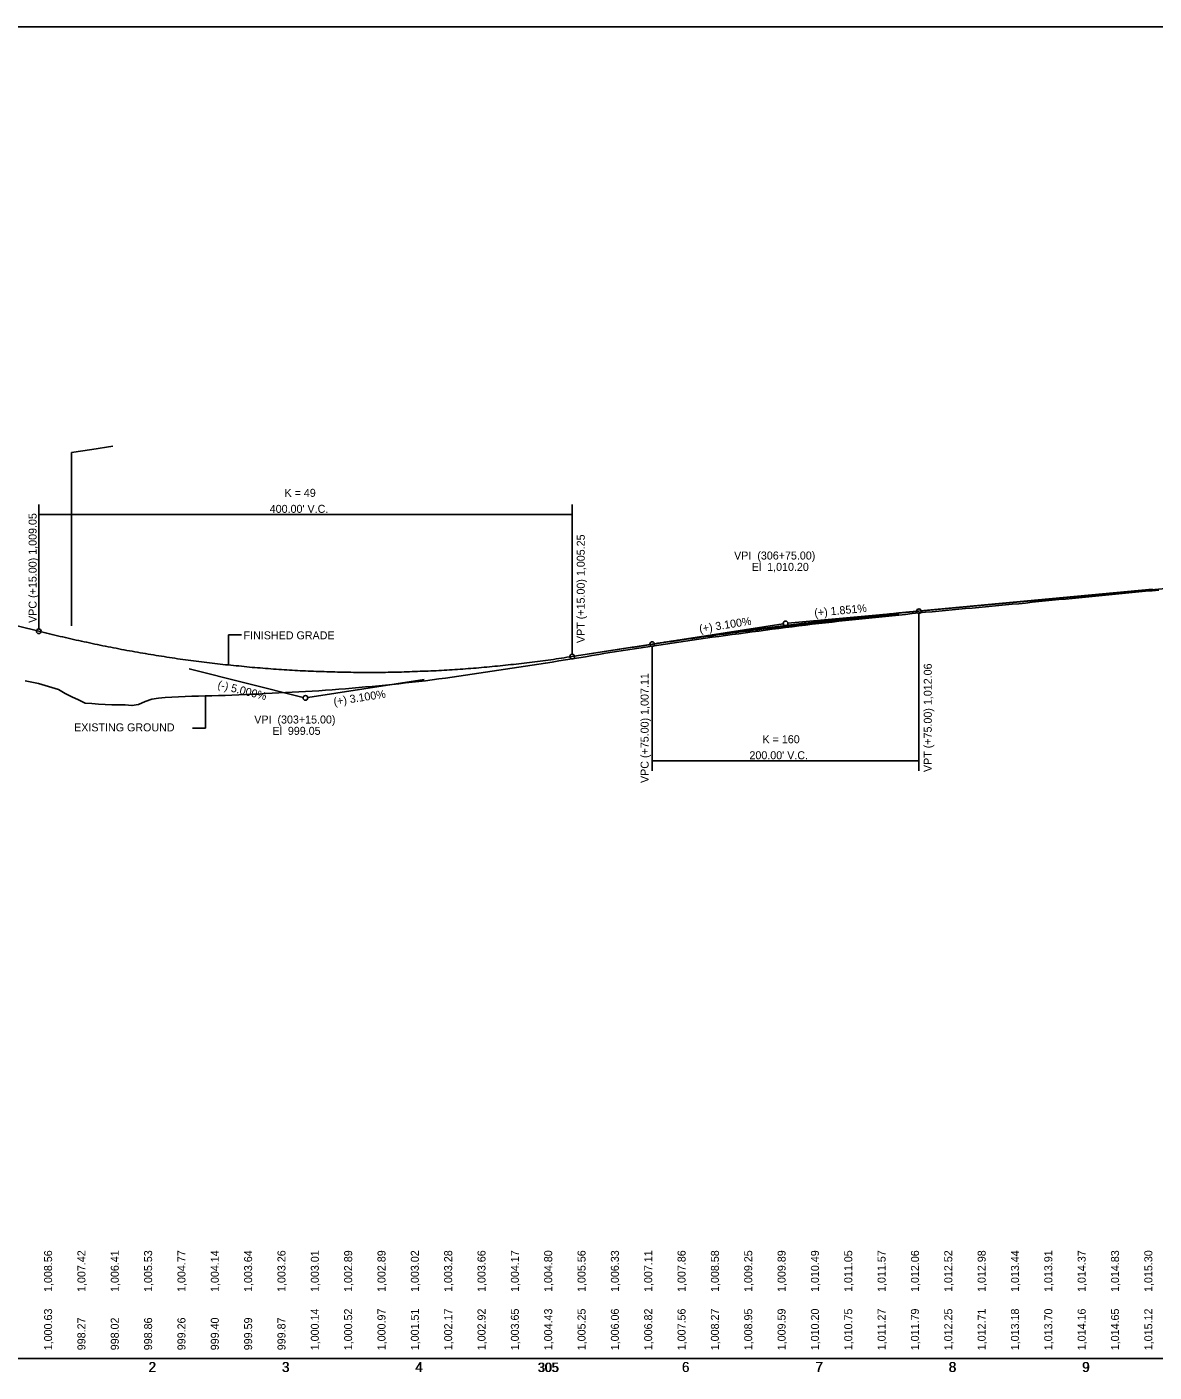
# Model space of a CAD drawing. Extents: x 112 to 16977479, y 1011 to 12562669.
# Drawn here: x 16974487 to 16975332, y 12561659 to 12562667 of the extents above; entities that cross this region are included whole.
import ezdxf

# ---------------------------------------------------------------- set-up
doc = ezdxf.new("R2010")
doc.units = 0
for name, color, linetype in [('Default', 7, 'Continuous'), ('RD_DDB_Ex_Tx', 7, 'Continuous'), ('RD_DDB_GradeTX', 7, 'Continuous'), ('RD_DDB_PI', 7, 'Continuous'), ('RD_DDB_Pr_Tx', 7, 'Continuous'), ('RD_DDB_Profile_EX', 7, 'Continuous'), ('RD_DDB_Profile_PR', 7, 'Continuous'), ('RD_DDB_StaTX', 7, 'Continuous'), ('RD_DDB_StripGrade_EX', 7, 'Continuous'), ('RD_DDB_StripGrade_PR', 7, 'Continuous'), ('RD_DDB_VCLbl', 7, 'Continuous'), ('RD_GPK_Profile_Cell', 7, 'Continuous'), ('RD_Sketch1', 7, 'Continuous')]:
    doc.layers.add(name, color=color, linetype=linetype)

msp = doc.modelspace()

# ---------------------------------------------------------------- linework, layer by layer
at = {"layer": 'Default'}
for p, q in [((16975140.4, 12562227.9), (16975330.4, 12562245.7)), ((16974895.4, 12562195.2), (16974940.4, 12562202.1))]:
    msp.add_line(p, q, dxfattribs=at)
msp.add_lwpolyline([(16974478.7, 12561668.9), (16975978.7, 12561668.9), (16975978.7, 12562667.2), (16974478.7, 12562667.2)], close=True, dxfattribs=at)
msp.add_open_spline([(16974940.4, 12562202.1), (16975040.4, 12562217.6), (16975140.4, 12562227)], degree=2, dxfattribs=at)
at = {"layer": 'RD_DDB_Ex_Tx'}
for p, q in [((16974620.5, 12562141.6), (16974620.5, 12562165.5)), ((16974610.8, 12562141.6), (16974620.5, 12562141.6))]:
    msp.add_line(p, q, dxfattribs=at)
at = {"layer": 'RD_DDB_PI'}
for p, q in [((16975145, 12562228.3), (16975057.1, 12562220.1)), ((16974966.5, 12562206.2), (16975053.7, 12562219.7)), ((16974608.1, 12562186), (16974693.7, 12562164.6)), ((16974784.3, 12562177.9), (16974697.1, 12562164.4))]:
    msp.add_line(p, q, dxfattribs=at)
for centre in [(16975055.4, 12562220), (16974695.4, 12562164.2)]:
    msp.add_circle(centre, 1.75, dxfattribs=at)
at = {"layer": 'RD_DDB_Pr_Tx'}
for p, q in [((16974647.5, 12562211.4), (16974637.6, 12562211.4)), ((16974637.6, 12562211.4), (16974637.6, 12562188.9))]:
    msp.add_line(p, q, dxfattribs=at)
at = {"layer": 'RD_DDB_Profile_EX'}
for points in [[(16975115.3, 12562223.8), (16975120.3, 12562224.3), (16975125.3, 12562224.8), (16975130.3, 12562225.3), (16975135.3, 12562225.8), (16975140.3, 12562226.3), (16975145.3, 12562226.8), (16975150.3, 12562227.4), (16975155.3, 12562227.9), (16975160.3, 12562228.4), (16975165.3, 12562228.8), (16975170.3, 12562229.3), (16975175.3, 12562229.7), (16975180.3, 12562230.2), (16975185.3, 12562230.6), (16975190.3, 12562231.1), (16975195.3, 12562231.5), (16975200.3, 12562232), (16975205.3, 12562232.5), (16975210.3, 12562232.9), (16975215.3, 12562233.4), (16975220.3, 12562233.9), (16975225.3, 12562234.4), (16975230.3, 12562234.8), (16975235.3, 12562235.3), (16975240.3, 12562235.9), (16975245.3, 12562236.4), (16975250.3, 12562236.9), (16975255.3, 12562237.4), (16975260.3, 12562237.9), (16975265.3, 12562238.3), (16975270.3, 12562238.8), (16975275.3, 12562239.3), (16975280.3, 12562239.7), (16975285.3, 12562240.2), (16975290.3, 12562240.7), (16975295.3, 12562241.2), (16975300.3, 12562241.7), (16975305.3, 12562242.2), (16975310.3, 12562242.7), (16975315.3, 12562243.2), (16975320.3, 12562243.6), (16975325.3, 12562244.1), (16975330.3, 12562244.5), (16975335.3, 12562244.9)], [(16974615.3, 12562165.5), (16974620.3, 12562165.7), (16974625.3, 12562165.8), (16974630.3, 12562166), (16974635.3, 12562166.1), (16974640.3, 12562166.3), (16974645.3, 12562166.5), (16974650.3, 12562166.7), (16974655.3, 12562166.9), (16974660.3, 12562167.1), (16974665.3, 12562167.4), (16974670.3, 12562167.7), (16974675.3, 12562168), (16974680.3, 12562168.3), (16974685.3, 12562168.5), (16974690.3, 12562168.7), (16974695.3, 12562169), (16974700.3, 12562169.3), (16974705.3, 12562169.6), (16974710.3, 12562170), (16974715.3, 12562170.3), (16974720.3, 12562170.7), (16974725.3, 12562171.1), (16974730.3, 12562171.5), (16974735.3, 12562172), (16974740.3, 12562172.4), (16974745.3, 12562172.8), (16974750.3, 12562173.3), (16974755.3, 12562173.8), (16974760.3, 12562174.3), (16974765.3, 12562174.8), (16974770.3, 12562175.4), (16974775.3, 12562175.9), (16974780.3, 12562176.5), (16974785.3, 12562177.1), (16974790.3, 12562177.8), (16974795.3, 12562178.5), (16974800.3, 12562179.1), (16974805.3, 12562179.8), (16974810.3, 12562180.5), (16974815.3, 12562181.2), (16974820.3, 12562182), (16974825.3, 12562182.8), (16974830.3, 12562183.5), (16974835.3, 12562184.3), (16974840.3, 12562185), (16974845.3, 12562185.7), (16974850.3, 12562186.5), (16974855.3, 12562187.2), (16974860.3, 12562187.9), (16974865.3, 12562188.7), (16974870.3, 12562189.4), (16974875.3, 12562190.3), (16974880.3, 12562191.1), (16974885.3, 12562191.9), (16974890.3, 12562192.7), (16974895.3, 12562193.5), (16974900.3, 12562194.3), (16974905.3, 12562195.1), (16974910.3, 12562196), (16974915.3, 12562196.8), (16974920.3, 12562197.6), (16974925.3, 12562198.4), (16974930.3, 12562199.2), (16974935.3, 12562200), (16974940.3, 12562200.7), (16974945.3, 12562201.5), (16974950.3, 12562202.2), (16974955.3, 12562203), (16974960.3, 12562203.7), (16974965.3, 12562204.5), (16974970.3, 12562205.2), (16974975.3, 12562206), (16974980.3, 12562206.7), (16974985.3, 12562207.4), (16974990.3, 12562208.2), (16974995.3, 12562208.9), (16975000.3, 12562209.6), (16975005.3, 12562210.3), (16975010.3, 12562211), (16975015.3, 12562211.7), (16975020.3, 12562212.3), (16975025.3, 12562213), (16975030.3, 12562213.6), (16975035.3, 12562214.3), (16975040.3, 12562214.9), (16975045.3, 12562215.6), (16975050.3, 12562216.2), (16975055.3, 12562216.9), (16975060.3, 12562217.5), (16975065.3, 12562218.2), (16975070.3, 12562218.8), (16975075.3, 12562219.4), (16975080.3, 12562219.9), (16975085.3, 12562220.5), (16975090.3, 12562221), (16975095.3, 12562221.6), (16975100.3, 12562222.1), (16975105.3, 12562222.7), (16975110.3, 12562223.2), (16975115.3, 12562223.8)], [(16974485.3, 12562177), (16974490.3, 12562175.9), (16974495.3, 12562174.9), (16974500.3, 12562173.5), (16974505.3, 12562172.1), (16974510.3, 12562170.4), (16974515.3, 12562167.5), (16974520.3, 12562165), (16974525.3, 12562162.8), (16974530.3, 12562160.3), (16974535.3, 12562159.9), (16974540.3, 12562159.6), (16974545.3, 12562159.3), (16974550.3, 12562159), (16974555.3, 12562159), (16974560.3, 12562159.1), (16974565.3, 12562158.4), (16974570.3, 12562159.3), (16974575.3, 12562161.5), (16974580.3, 12562163.2), (16974585.3, 12562164), (16974590.3, 12562164.5), (16974595.3, 12562164.7), (16974600.3, 12562165), (16974605.3, 12562165.2), (16974610.3, 12562165.4), (16974615.3, 12562165.5)]]:
    msp.add_lwpolyline(points, dxfattribs=at)
at = {"layer": 'RD_DDB_Profile_PR'}
for p, q in [((16975155.4, 12562229.2), (16975340.4, 12562246.3)), ((16974450.4, 12562225.4), (16974495.4, 12562214.2)), ((16974895.4, 12562195.2), (16974955.4, 12562204.5))]:
    msp.add_line(p, q, dxfattribs=at)
for points in [[(16974955.4, 12562204.5), (16974959.4, 12562205.1), (16974963.4, 12562205.7), (16974967.4, 12562206.3), (16974971.4, 12562206.9), (16974975.4, 12562207.5), (16974979.4, 12562208.1), (16974983.4, 12562208.7), (16974987.4, 12562209.3), (16974991.4, 12562209.8), (16974995.4, 12562210.4), (16974999.4, 12562211), (16975003.4, 12562211.5), (16975007.4, 12562212.1), (16975011.4, 12562212.7), (16975015.4, 12562213.2), (16975019.4, 12562213.7), (16975023.4, 12562214.3), (16975027.4, 12562214.8), (16975031.4, 12562215.3), (16975035.4, 12562215.9), (16975039.4, 12562216.4), (16975043.4, 12562216.9), (16975047.4, 12562217.4), (16975051.4, 12562217.9), (16975055.4, 12562218.4), (16975059.4, 12562218.9), (16975063.4, 12562219.4), (16975067.4, 12562219.9), (16975071.4, 12562220.3), (16975075.4, 12562220.8), (16975079.4, 12562221.3), (16975083.4, 12562221.7), (16975087.4, 12562222.2), (16975091.4, 12562222.7), (16975095.4, 12562223.1), (16975099.4, 12562223.5), (16975103.4, 12562224), (16975107.4, 12562224.4), (16975111.4, 12562224.8), (16975115.4, 12562225.3), (16975119.4, 12562225.7), (16975123.4, 12562226.1), (16975127.4, 12562226.5), (16975131.4, 12562226.9), (16975135.4, 12562227.3), (16975139.4, 12562227.7), (16975143.4, 12562228.1), (16975147.4, 12562228.5), (16975151.4, 12562228.8), (16975155.4, 12562229.2)], [(16974495.4, 12562214.2), (16974503.4, 12562212.2), (16974511.4, 12562210.3), (16974519.4, 12562208.5), (16974527.4, 12562206.7), (16974535.4, 12562205), (16974543.4, 12562203.3), (16974551.4, 12562201.8), (16974559.4, 12562200.2), (16974567.4, 12562198.8), (16974575.4, 12562197.4), (16974583.4, 12562196.1), (16974591.4, 12562194.8), (16974599.4, 12562193.6), (16974607.4, 12562192.5), (16974615.4, 12562191.5), (16974623.4, 12562190.5), (16974631.4, 12562189.5), (16974639.4, 12562188.7), (16974647.4, 12562187.9), (16974655.4, 12562187.1), (16974663.4, 12562186.5), (16974671.4, 12562185.8), (16974679.4, 12562185.3), (16974687.4, 12562184.8), (16974695.4, 12562184.4), (16974703.4, 12562184.1), (16974711.4, 12562183.8), (16974719.4, 12562183.6), (16974727.4, 12562183.4), (16974735.4, 12562183.3), (16974743.4, 12562183.3), (16974751.4, 12562183.3), (16974759.4, 12562183.4), (16974767.4, 12562183.6), (16974775.4, 12562183.9), (16974783.4, 12562184.2), (16974791.4, 12562184.5), (16974799.4, 12562184.9), (16974807.4, 12562185.4), (16974815.4, 12562186), (16974823.4, 12562186.6), (16974831.4, 12562187.3), (16974839.4, 12562188.1), (16974847.4, 12562188.9), (16974855.4, 12562189.8), (16974863.4, 12562190.7), (16974871.4, 12562191.7), (16974879.4, 12562192.8), (16974887.4, 12562194), (16974895.4, 12562195.2)]]:
    msp.add_spline(points, degree=3, dxfattribs=at)
at = {"layer": 'RD_DDB_VCLbl'}
for p, q in [((16974495.4, 12562309.2), (16974495.4, 12562215.9)), ((16974895.4, 12562309.2), (16974895.4, 12562196.9)), ((16974495.4, 12562301.7), (16974895.4, 12562301.7)), ((16975155.4, 12562109.5), (16975155.4, 12562227.5)), ((16974955.4, 12562109.5), (16974955.4, 12562202.7)), ((16974955.4, 12562117), (16975155.4, 12562117))]:
    msp.add_line(p, q, dxfattribs=at)
for centre in [(16975155.4, 12562229.2), (16974495.4, 12562214.2), (16974955.4, 12562204.5), (16974895.4, 12562195.2)]:
    msp.add_circle(centre, 1.75, dxfattribs=at)
at = {"layer": 'RD_GPK_Profile_Cell'}
msp.add_line((16973115.3, 12561668.9), (16977337.9, 12561668.9), dxfattribs=at)
at = {"layer": 'RD_Sketch1'}
for p, q in [((16974519.9, 12562348.2), (16974535.1, 12562350.3)), ((16974519.9, 12562348.2), (16974519.9, 12562308.2)), ((16974535.1, 12562350.3), (16974550.9, 12562352.8)), ((16974519.9, 12562308.2), (16974519.9, 12562218.2))]:
    msp.add_line(p, q, dxfattribs=at)

# ---------------------------------------------------------------- texts
at = {"layer": 'RD_DDB_Ex_Tx'}
msp.add_text('EXISTING GROUND', height=6, dxfattribs=at).set_placement((16974521.9, 12562139.1))
at = {"layer": 'RD_DDB_GradeTX'}
for s, rotation, p in [('(+) 1.851%', 5.2881, (16975077.2, 12562225)), ('(+) 3.100%', 8.8105, (16974991.1, 12562213)), ('(-) 5.000%', 345.9641, (16974629.1, 12562171.5)), ('(+) 3.100%', 8.8105, (16974716.9, 12562158.4))]:
    msp.add_text(s, height=6, rotation=rotation, dxfattribs=at).set_placement(p)
at = {"layer": 'RD_DDB_PI'}
for s, p in [('VPI  (306+75.00)', (16975016.8, 12562267.9)), ('El  1,010.20', (16975030, 12562259.4)), ('VPI  (303+15.00)', (16974657, 12562145)), ('El  999.05', (16974670.6, 12562136.5))]:
    msp.add_text(s, height=6, dxfattribs=at).set_placement(p)
at = {"layer": 'RD_DDB_Pr_Tx'}
msp.add_text('FINISHED GRADE', height=6, dxfattribs=at).set_placement((16974649, 12562208.1))
at = {"layer": 'RD_DDB_StaTX'}
for s, height, p in [('2', 7.5, (16974577.6, 12561658.9)), ('2', 7.5, (16974577.6, 12561658.9)), ('2', 7.5, (16974578, 12561658.9)), ('3', 7.5, (16974677.6, 12561658.9)), ('3', 7.5, (16974677.6, 12561658.9)), ('3', 7.5, (16974678, 12561658.9)), ('4', 7.5, (16974777.6, 12561658.9)), ('4', 7.5, (16974777.6, 12561658.9)), ('4', 7.5, (16974778, 12561658.9)), ('305', 7, (16974869.4, 12561658.9)), ('305', 7, (16974869.4, 12561658.9)), ('305', 7, (16974870, 12561658.9)), ('6', 7.5, (16974977.6, 12561658.9)), ('6', 7.5, (16974977.6, 12561658.9)), ('6', 7.5, (16974977.8, 12561658.9)), ('7', 7.5, (16975077.6, 12561658.9)), ('7', 7.5, (16975077.6, 12561658.9)), ('7', 7.5, (16975078, 12561658.9)), ('8', 7.5, (16975177.6, 12561658.9)), ('8', 7.5, (16975177.6, 12561658.9)), ('8', 7.5, (16975178, 12561658.9)), ('9', 7.5, (16975277.6, 12561658.9)), ('9', 7.5, (16975277.6, 12561658.9)), ('9', 7.5, (16975278, 12561658.9))]:
    msp.add_text(s, height=height, dxfattribs=at).set_placement(p)
at = {"layer": 'RD_DDB_StripGrade_EX'}
for s, p in [('1,000.63', (16974505.4, 12561675.2)), ('1,000.14', (16974705.4, 12561675.2)), ('1,000.52', (16974730.4, 12561675.2)), ('1,000.97', (16974755.4, 12561675.2)), ('1,001.51', (16974780.4, 12561675.2)), ('1,002.17', (16974805.4, 12561675.2)), ('1,002.92', (16974830.4, 12561675.2)), ('1,003.65', (16974855.4, 12561675.2)), ('1,004.43', (16974880.4, 12561675.2)), ('1,005.25', (16974905.4, 12561675.2)), ('1,006.06', (16974930.4, 12561675.2)), ('1,006.82', (16974955.4, 12561675.2)), ('1,007.56', (16974980.4, 12561675.2)), ('1,008.27', (16975005.4, 12561675.2)), ('1,008.95', (16975030.4, 12561675.2)), ('1,009.59', (16975055.4, 12561675.2)), ('1,010.20', (16975080.4, 12561675.2)), ('1,010.75', (16975105.4, 12561675.2)), ('1,011.27', (16975130.4, 12561675.2)), ('1,011.79', (16975155.4, 12561675.2)), ('1,012.25', (16975180.4, 12561675.2)), ('1,012.71', (16975205.4, 12561675.2)), ('1,013.18', (16975230.4, 12561675.2)), ('1,013.70', (16975255.4, 12561675.2)), ('1,014.16', (16975280.4, 12561675.2)), ('1,014.65', (16975305.4, 12561675.2)), ('1,015.12', (16975330.4, 12561675.2)), ('998.27', (16974530.4, 12561675.2)), ('998.02', (16974555.4, 12561675.2)), ('998.86', (16974580.4, 12561675.2)), ('999.26', (16974605.4, 12561675.2)), ('999.40', (16974630.4, 12561675.2)), ('999.59', (16974655.4, 12561675.2)), ('999.87', (16974680.4, 12561675.2))]:
    msp.add_text(s, height=6, rotation=90, dxfattribs=at).set_placement(p)
at = {"layer": 'RD_DDB_StripGrade_PR'}
for s, p in [('1,008.56', (16974505.4, 12561718.9)), ('1,007.42', (16974530.4, 12561718.9)), ('1,006.41', (16974555.4, 12561718.9)), ('1,005.53', (16974580.4, 12561718.9)), ('1,004.77', (16974605.4, 12561718.9)), ('1,004.14', (16974630.4, 12561718.9)), ('1,003.64', (16974655.4, 12561718.9)), ('1,003.26', (16974680.4, 12561718.9)), ('1,003.01', (16974705.4, 12561718.9)), ('1,002.89', (16974730.4, 12561718.9)), ('1,002.89', (16974755.4, 12561718.9)), ('1,003.02', (16974780.4, 12561718.9)), ('1,003.28', (16974805.4, 12561718.9)), ('1,003.66', (16974830.4, 12561718.9)), ('1,004.17', (16974855.4, 12561718.9)), ('1,004.80', (16974880.4, 12561718.9)), ('1,005.56', (16974905.4, 12561718.9)), ('1,006.33', (16974930.4, 12561718.9)), ('1,007.11', (16974955.4, 12561718.9)), ('1,007.86', (16974980.4, 12561718.9)), ('1,008.58', (16975005.4, 12561718.9)), ('1,009.25', (16975030.4, 12561718.9)), ('1,009.89', (16975055.4, 12561718.9)), ('1,010.49', (16975080.4, 12561718.9)), ('1,011.05', (16975105.4, 12561718.9)), ('1,011.57', (16975130.4, 12561718.9)), ('1,012.06', (16975155.4, 12561718.9)), ('1,012.52', (16975180.4, 12561718.9)), ('1,012.98', (16975205.4, 12561718.9)), ('1,013.44', (16975230.4, 12561718.9)), ('1,013.91', (16975255.4, 12561718.9)), ('1,014.37', (16975280.4, 12561718.9)), ('1,014.83', (16975305.4, 12561718.9)), ('1,015.30', (16975330.4, 12561718.9))]:
    msp.add_text(s, height=6, rotation=90, dxfattribs=at).set_placement(p)
at = {"layer": 'RD_DDB_VCLbl'}
for s, p in [('K = 49', (16974679.7, 12562314.9)), ("400.00' V.C.", (16974668.6, 12562302.9)), ('K = 160', (16975038.1, 12562130.2)), ("200.00' V.C.", (16975028.3, 12562118.2))]:
    msp.add_text(s, height=6, dxfattribs=at).set_placement(p)
for s, p in [('VPC (+15.00) 1,009.05', (16974493.8, 12562220.4)), ('VPT (+15.00) 1,005.25', (16974904.8, 12562205.3)), ('VPT (+75.00) 1,012.06', (16975165, 12562108.6)), ('VPC (+75.00) 1,007.11', (16974952.7, 12562100.4))]:
    msp.add_text(s, height=6, rotation=90, dxfattribs=at).set_placement(p)

doc.saveas('drawing.dxf')
